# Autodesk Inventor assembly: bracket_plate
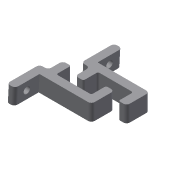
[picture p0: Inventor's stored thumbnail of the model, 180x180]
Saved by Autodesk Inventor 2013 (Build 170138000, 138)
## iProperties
Created: 2013-11
Part Number: bracket_plate
Document SubType Name: Assembly
Designer: Jonas
Author: Jonas
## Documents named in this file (3)
- C:\Users\Jonas\Documents\Inventor\Polplot\bracket_plate.iam
- C:\Users\Jonas\Documents\Inventor\Polplot\side_bracket.ipt
- C:\Users\Jonas\Documents\Inventor\Polplot\side_bracket_MIR.ipt
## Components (2 placed, 2 different names)
1. side_bracket:1 — Mate:1
2. side_bracket_MIR:1 — Mate:2
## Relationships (2: Mate 2)
- Mate:1: side_bracket:1
- Mate:2: side_bracket_MIR:1
